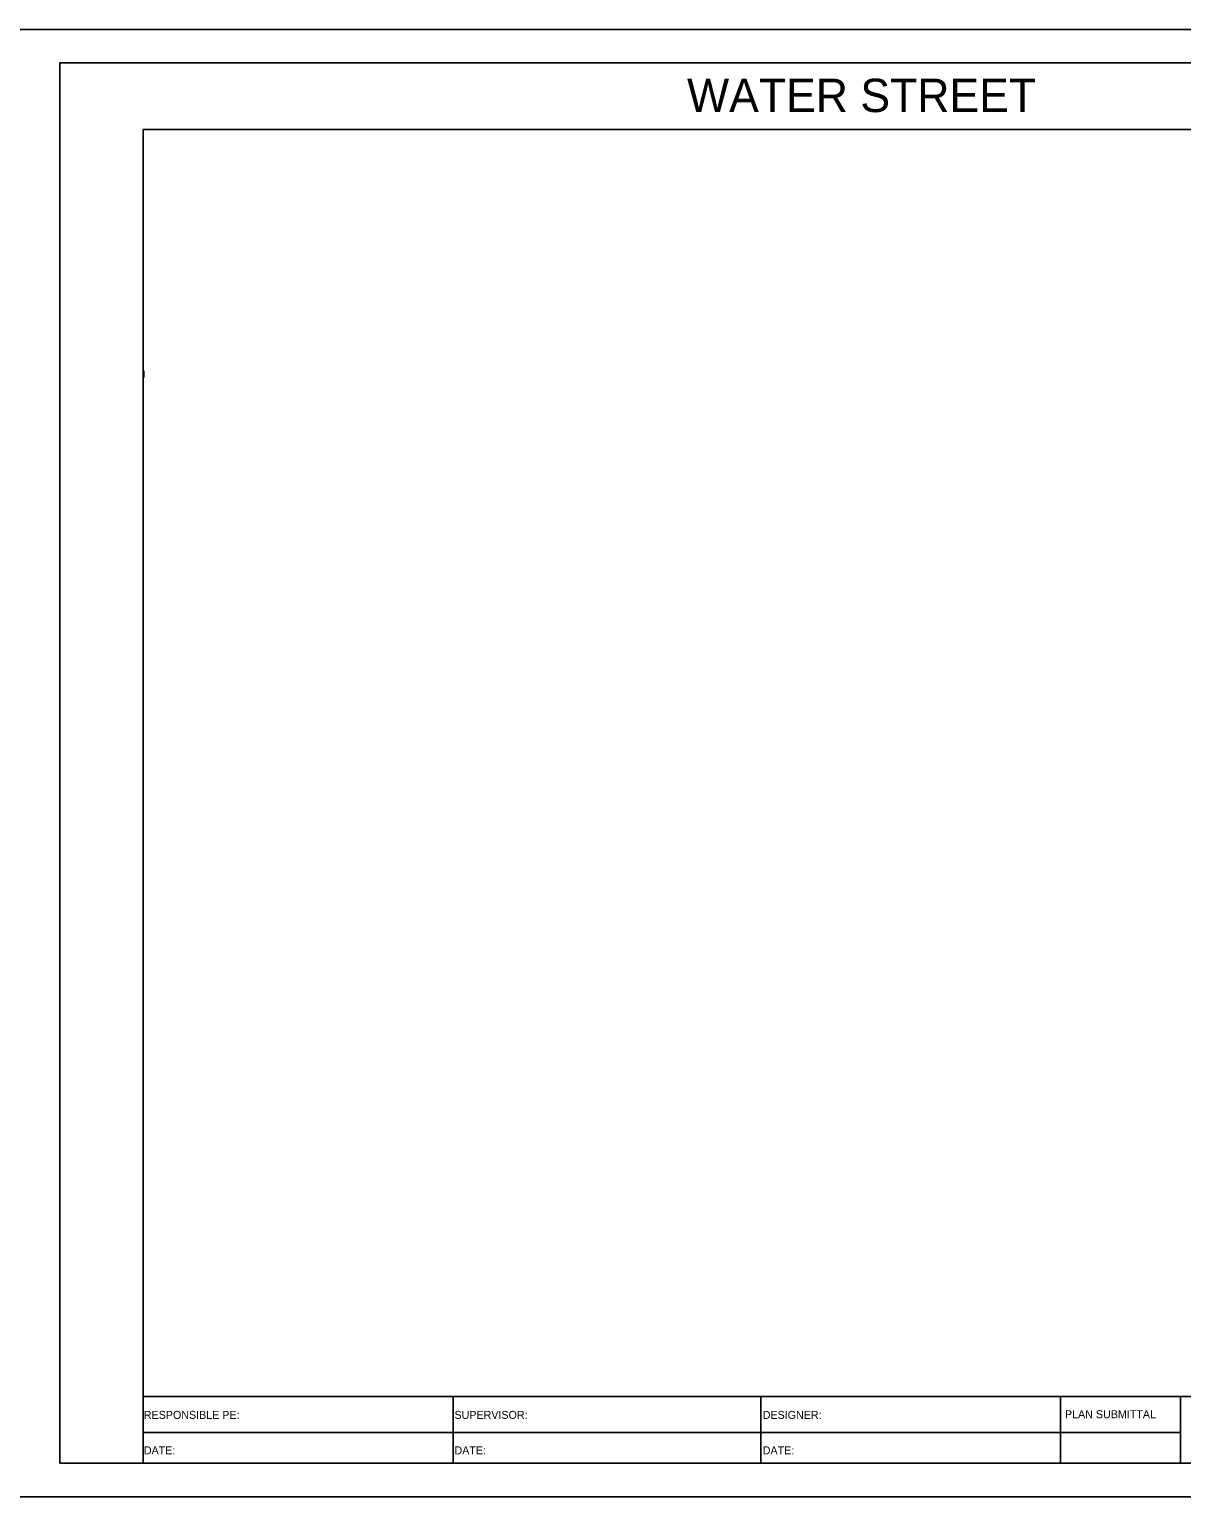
# Model space of a CAD drawing. Extents: x 1797478 to 1808916, y 246529 to 250952.
# Drawn here: x 1803143.9 to 1803316.8, y 250064.4 to 250284.4 of the extents above; entities that cross this region are included whole.
import ezdxf

# ---------------------------------------------------------------- set-up
doc = ezdxf.new("R2010")
doc.units = 0
for name, color, linetype in [('2', 7, 'Continuous'), ('ANNO-SHT', 7, 'Continuous'), ('ANNO-TXT', 7, 'Continuous'), ('AXIS', 7, 'Continuous'), ('DRAINAGE', 7, 'Continuous'), ('Level 1', 7, 'Continuous'), ('Level 62', 7, 'Continuous'), ('SHT-BDR', 7, 'Continuous'), ('SHT-BNDRY', 7, 'Continuous')]:
    doc.layers.add(name, color=color, linetype=linetype)

# ---------------------------------------------------------------- blocks, each defined once
blk = doc.blocks.new('SC47208')
at = {"layer": 'Level 1'}
blk.add_line((0, 0), (0, 0), dxfattribs=at)

msp = doc.modelspace()

# ---------------------------------------------------------------- linework, layer by layer
at = {"layer": '2'}
msp.add_lwpolyline([(1803161.12, 250233.21), (1803161.1, 250232.21)], dxfattribs=at)
msp.add_lwpolyline([(1803161.12, 250233.21), (1803161.1, 250232.21)], dxfattribs=at)
at = {"layer": 'AXIS'}
msp.add_line((1803161, 250189.42), (1803161, 250189.43), dxfattribs=at)
at = {"layer": 'Level 62'}
msp.add_lwpolyline([(1803136, 250064.42), (1803476, 250064.42), (1803476, 250284.42), (1803136, 250284.42)], close=True, dxfattribs=at)
at = {"layer": 'SHT-BDR'}
msp.add_lwpolyline([(1803161, 250079.43), (1803461, 250079.43), (1803461, 250269.43), (1803161, 250269.43)], close=True, dxfattribs=at)
at = {"layer": 'SHT-BNDRY'}
for p, q in [((1803161, 250069.42), (1803161, 250079.43)), ((1803207.52, 250079.43), (1803207.52, 250069.42)), ((1803253.67, 250069.42), (1803253.67, 250079.43)), ((1803298.59, 250069.42), (1803298.59, 250079.43)), ((1803316.63, 250069.42), (1803316.63, 250079.43)), ((1803161, 250074.03), (1803316.63, 250074.03))]:
    msp.add_line(p, q, dxfattribs=at)
msp.add_lwpolyline([(1803148.5, 250069.42), (1803471, 250069.42), (1803471, 250279.42), (1803148.5, 250279.42)], close=True, dxfattribs=at)

# ---------------------------------------------------------------- block references
at = {"layer": 'DRAINAGE', "xscale": 0.2, "yscale": 0.20000000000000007, "rotation": -116.41666666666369}
msp.add_blockref('SC47208', (1803311.32, 250274.62), dxfattribs=at)
msp.add_blockref('SC47208', (1803311.32, 250274.62), dxfattribs=at)

# ---------------------------------------------------------------- texts
at = {"layer": 'ANNO-SHT'}
msp.add_text('         WATER STREET         ', height=4.9995, rotation=360, dxfattribs=at).set_placement((1803225.87, 250272.02))
at = {"layer": 'ANNO-TXT'}
for s, p in [('RESPONSIBLE PE:', (1803161.1, 250076.08)), ('SUPERVISOR:', (1803207.7, 250076.08)), ('DESIGNER:', (1803253.94, 250076.08)), ('PLAN SUBMITTAL', (1803299.28, 250076.18)), ('DATE:', (1803161.1, 250070.76)), ('DATE:', (1803207.7, 250070.76)), ('DATE:', (1803253.94, 250070.76))]:
    msp.add_text(s, height=1.2, rotation=360, dxfattribs=at).set_placement(p)

doc.saveas('drawing.dxf')
